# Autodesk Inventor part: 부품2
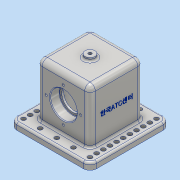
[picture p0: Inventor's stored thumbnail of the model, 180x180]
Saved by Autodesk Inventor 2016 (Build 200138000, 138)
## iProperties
Created: 2018-11
Part Number: 부품2
Material: 알루미늄 6061
Document SubType Name: Modeling
Designer: PC-2
Density: 2.7 g/cm^3
Appearance: 알루미늄 - 평지
Author: PC-2
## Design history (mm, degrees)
sketch "스케치1"
  geometry: L1 (-60, 60)-(60, 60); L2 (60, 60)-(60, -60); L3 (60, -60)-(-60, -60); L4 (-60, -60)-(-60, 60); L5 (-60, 60)-(60, -60); L6 (60, 60)-(-60, -60); 1 further point
  constraints: 12 end point, 2 midpoint, 2 parallel, 1 horizontal, 1 perpendicular
  dimensions: "d0" = 120 distance of L1.start L1.end; "d1" = 120 distance of L3.end L1.start
extrude "돌출1" new body sketch "스케치1" distance "d2" = 10; taper "d3" = 0 deg
sketch "스케치2"
  geometry: L1 (-40, 40)-(40, 40); L2 (40, 40)-(40, -40); L3 (40, -40)-(-40, -40); L4 (-40, -40)-(-40, 40); L5 (-40, 40)-(40, -40); L6 (40, 40)-(-40, -40); 1 further point
  constraints: 12 end point, 2 midpoint, 2 parallel, 1 horizontal, 1 perpendicular
  dimensions: "d4" = 80 distance of L1.start L1.end; "d5" = 80 distance of L3.end L1.start
extrude "돌출2" join sketch "스케치2" distance "d6" = 80; taper "d7" = 0 deg
sketch "스케치3"
  geometry: L1 (23, -30)-(-23, -30); L2 (-23, -30)-(-23, 30); L3 (-23, 30)-(23, 30); L4 (23, 30)-(23, -30); L5 (23, -30)-(-23, 30); L6 (-23, -30)-(23, 30); 1 further point
  constraints: 12 end point, 2 midpoint, 2 parallel, 1 horizontal, 1 perpendicular
  dimensions: "d8" = 46 distance of L1.start L1.end; "d9" = 60 distance of L3.end L1.start
extrude "돌출3" cut sketch "스케치3" distance "d10" = 80; taper "d11" = 0 deg
sketch "스케치4"
  geometry: L1 (10, 100)-(10, -20) reference; 2 further points
  dimensions: "d12" = 48 distance from line of point (-38, 40) L1
hole "구멍1" sketch "스케치4" at (-38, 40) diameter "d13" = 33; stored, may be unused: countersink angle "d17" = 90 deg, drill point angle "d19" = 0 deg; dims "d14" = 6, "d15" = 40, "d16" = 14, "d18" = 3
node "작업 평면1"
sketch "스케치5"
  geometry: C1 r 7.5 at (0, 0); 1 further point
  constraints: 1 centre point, 1 coincident
  dimensions: "d21" = 15 diameter of C1
extrude "돌출4" join sketch "스케치5" stored distance "d22" = 80; taper "d23" = 0 deg
fillet "모깎기1" dims "d24" = 10
hole "구멍2" diameter "d27" = 4.917; stored, may be unused: countersink angle "d31" = 90 deg, drill point angle "d33" = 0 deg; dims "d28" = 20, "d29" = 4, "d30" = 2, "d32" = 25.1, "d92" = 10, "d93" = 10
sketch "스케치6" dims "d34" = 52
  geometry: C1 r 20 at (-38, 40) reference; 3 further points
  constraints: 1 coincident, 1 horizontal alignment, 2 other
hole "구멍3" sketch "스케치6" at (-64, 40) diameter "d35" = 3.242; stored, may be unused: countersink angle "d39" = 90 deg, drill point angle "d41" = 118 deg; dims "d36" = 8, "d37" = 4, "d38" = 2, "d40" = 10
sketch "스케치7"
  geometry: L1 (-23, 30)-(-23, -30) reference; L2 (-23, -30)-(23, -30) reference; 2 further points
  dimensions: "d45" = 50 horizontal distance of point (-50, -50) point (0, 0); "d46" = 50 horizontal distance of point (-50, -50) point (0, 0)
hole "구멍4" sketch "스케치7" at (-50, -50) diameter "d47" = 6.6; stored, may be unused: countersink angle "d51" = 90 deg, drill point angle "d53" = 0 deg; dims "d48" = 8, "d49" = 4, "d50" = 2, "d52" = 10
sketch "스케치8"
  geometry: C1 r 3.3 at (-50, -50) reference; 11 further points
  constraints: 1 vertical alignment
  dimensions: "d54" = 10 distance of C1.centre point (-40, -50); "d55" = 10 distance of point (-30, -50) point (-40, -50); "d56" = 10 distance of point (-20, -50) point (-30, -50); "d57" = 10 distance of point (-20, -50) point (-10, -50); "d59" = 10 distance of point (0, -50) point (10, -50); "d60" = 10 distance of point (10, -50) point (20, -50); "d61" = 10 distance of point (20, -50) point (30, -50); "d62" = 10 distance of point (40, -50) point (30, -50); "d63" = 10 distance of point (40, -50) point (50, -50)
hole "구멍5" sketch "스케치8" at (-40, -50), (-30, -50), (-20, -50), (0, -50), (10, -50), (20, -50), (40, -50), (50, -50), (-10, -50), (30, -50) diameter "d64" = 6.6; stored, may be unused: countersink angle "d68" = 90 deg, drill point angle "d70" = 0 deg; dims "d65" = 8, "d66" = 4, "d67" = 2, "d69" = 10
sketch "스케치9"
  geometry: C1 r 3.3 at (-50, 50) reference; C2 r 3.3 at (-50, -50) reference; 4 further points
  constraints: 1 horizontal alignment
  dimensions: "d71" = 25 distance of C1.centre point (-50, 25); "d72" = 25 distance of C2.centre point (-50, -25)
hole "구멍6" sketch "스케치9" at (-50, 0), (-50, 25), (-50, -25) diameter "d73" = 6.6; stored, may be unused: countersink angle "d77" = 90 deg, drill point angle "d79" = 0 deg; dims "d74" = 8, "d75" = 4, "d76" = 2, "d78" = 10
sketch "스케치10"
  geometry: L1 (-10, 10)-(90, 10) reference; 3 further points
  constraints: 1 midpoint, 1 vertical alignment, 1 other
  dimensions: "d80" = 48 distance from line of L1 point (40, -38)
feature "엠보싱1" sketch "스케치10" dims "d0" = 120, "d1" = 120, "d81" = 0.5, "d82" = 0
fillet "모깎기2" dims "d83" = 8
fillet "모깎기3" dims "d84" = 8
fillet "모깎기4" dims "d85" = 3
chamfer "모따기1" distance "d86" = 1; stored, may be unused: second distance "d87" = 2, angle "d88" = 45 deg
fillet "모깎기5" dims "d89" = 0.6
fillet "모깎기6" dims "d90" = 3
fillet "모깎기7" dims "d91" = 3
node "솔리드1"
mirror "대칭1"
pattern_circular "원형 패턴1" dims angle "d43" = 360 deg
mirror "대칭2"
mirror "대칭3"
mirror "대칭4"
other parameters: "d20" = 95
